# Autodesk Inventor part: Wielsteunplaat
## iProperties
Created: 2007-06
Part Number: Wielsteunplaat
Material: Steel
Document SubType Name: Modeling
Designer: Phil Trethewie
Author: Phil Trethewie
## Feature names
1. Extrusion1
2. Hole1
